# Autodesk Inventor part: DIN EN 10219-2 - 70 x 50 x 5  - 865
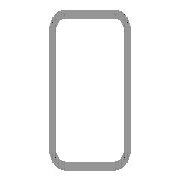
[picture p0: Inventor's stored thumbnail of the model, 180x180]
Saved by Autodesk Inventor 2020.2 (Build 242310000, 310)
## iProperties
Created: 2019-01
Part Number: DIN EN 10219-2 - 70 x 50 x 5  - 865
Material: Stahl, weich
Description: Kaltgeformte, geschweißte Baustahl-Hohlprofile aus unlegiertem Feinkorn-Baustahl
Document SubType Name: Modeling
Standard: DIN
Designer: lutzd
Standard Revision: 2006-07
Standards Organization: DIN
Language: de-DE
Size Designation: 70 x 50 x 5
Categories: <MemberInstance><Categories><Category DisplayName="Profile" InternalName="089c4875-fa83-4c05-b084-43b9cc11f5ed" Mnemonic="GRDR"><CategoryParameter DisplayName="
Stock Number: 70 x 50 x 5
Mass: 7021.22 g
Surface Area: 3606.76 cm^2
Volume: 894.423 cm^3
Density: 7.85 g/cm^3
Appearance: Semi-Polished(8)
_CCFamilyMember: 17
_CCFamilyDisplayName: DIN EN 10219-2 (Rechteckiges Hohlprofil - Kaltgeformt) - Kaltgeformte, geschweißte Baustahl-Hohlprofile aus unlegiertem Feinkorn-Baustahl
_FrameMemberDoc: Frame Member File
_Version: 15.0.0
_GetPNFromCC: 1
G_L: 865,000 mm
G_W: 50,000 mm
G_H: 70,000 mm
DocNumber: ADSK-014375
Folder: .
Mass: 7,021 kg
VLT_Material: Stahl, weich
+FD7447D9-C712-46D3-ADC1-A998DB6001B3+SCHNITTDETAIL1: Schnittwinkel 90,00 grd
Dimensions: 50x70x865 mm
IsCustomPart: 1
Title: Profil-Bauteil
Author: lutzd
Revision Number: -
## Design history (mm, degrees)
node "Startebene"
node "Endebene"
sketch "Skizze"
  geometry: L1 (-25, -25)-(-25, 25); L2 (-15, 35)-(15, 35); L3 (25, 25)-(25, -25); L4 (15, -35)-(-15, -35); L5 (-15, 30)-(15, 30); L6 (20, 25)-(20, -25); L7 (15, -30)-(-15, -30); L8 (-20, -25)-(-20, 25); L9 (0, 51.899)-(0, -51.899) reference; L10 (-37.899, 0)-(37.899, 0) reference; A1 r 10 centre (-15, -25) between (-25, -25) and (-15, -35); A2 r 10 centre (-15, 25) between (-15, 35) and (-25, 25); A3 r 10 centre (15, 25) between (25, 25) and (15, 35); A4 r 10 centre (15, -25) between (15, -35) and (25, -25); A5 r 5 centre (-15, 25) between (-15, 30) and (-20, 25); A6 r 5 centre (15, 25) between (20, 25) and (15, 30); A7 r 5 centre (15, -25) between (15, -30) and (20, -25); A8 r 5 centre (-15, -25) between (-20, -25) and (-15, -30)
  constraints: 16 end point, 16 point on circle, 8 centre point, 8 tangent, 4 parallel, 3 equal radius, 2 perpendicular, 7 other
  dimensions: "d7" = 10 radius of A1 (= G_IR); "d10" = 70 distance between parallel lines of L2 L4 (= G_H); "d11" = 50 distance between parallel lines of L1 L3 (= G_W); "d12" = 5 distance between parallel lines of L3 L6 (= G_T); "d15" = 35 distance between parallel lines of L2 L10 (= 0.5 x d10); "d16" = 25 distance between parallel lines of L9 L3 (= 0.5 x d11)
extrude "Körper" new body sketch "Skizze" stored distance "d3" = 865 (= G_L); taper "d4" = 0 deg
node "Driven Length"
  sketch "Sketch3"
    geometry: L1 (0, 0)-(10, 0) reference
    constraints: 2 end point, 1 horizontal
  workplane "Work Plane3"
  sketch "Sketch4"
    geometry: L1 (-2, 0)-(12, 0) reference; L2 (-2, 865)-(12, 865) reference
    dimensions: "d18" = 865 distance between parallel lines of L1 L2 (derived)
workplane "Arbeitsebene4"
feature "Trennen1"
sketch "Skizze5"
  geometry: L1 (865, 50)-(865, 0) reference; L2 (865, 25)-(688, 25); L3 (0, 50)-(0, 0) reference; L4 (0, 25)-(310, 25); 4 further points
  constraints: 4 end point, 2 coincident, 2 horizontal, 2 point on line, 1 midpoint
  dimensions: "d20" = 77 distance from line of L1 point (788, 25); "d21" = 100 distance of point (788, 25) point (688, 25); "d29" = 310 distance of L4.start L4.end; "d30" = 35 distance of point (275, 25) point (310, 25)
hole "Bohrung1" sketch "Skizze5" at (688, 25), (788, 25), (275, 25), (310, 25) diameter "d22" = 6.647; stored, may be unused: countersink angle "d26" = 90 deg, drill point angle "d28" = 118 deg; dims "d23" = 16, "d24" = 4, "d25" = 2, "d27" = 22.2
body "Solid1"
other parameters: "G_W" = 50 [user parameter; used in 1 equation term], "G_H" = 70 [user parameter; used in 1 equation term], "G_T" = 5 [user parameter; used in 1 equation term], "G_IR" = 10 [user parameter; used in 1 equation term], "G_L" = 865 (= d18) [user parameter; used in 1 equation term], "G_OFFSET_START" = 0 [user parameter; used in 1 equation term], "G_OFFSET_END" = -365 [user parameter; used in 1 equation term], "d13" = 0 (computed from G_OFFSET_START), "d14" = 865 (= G_OFFSET_END + B_L), "d17" = 90 deg
